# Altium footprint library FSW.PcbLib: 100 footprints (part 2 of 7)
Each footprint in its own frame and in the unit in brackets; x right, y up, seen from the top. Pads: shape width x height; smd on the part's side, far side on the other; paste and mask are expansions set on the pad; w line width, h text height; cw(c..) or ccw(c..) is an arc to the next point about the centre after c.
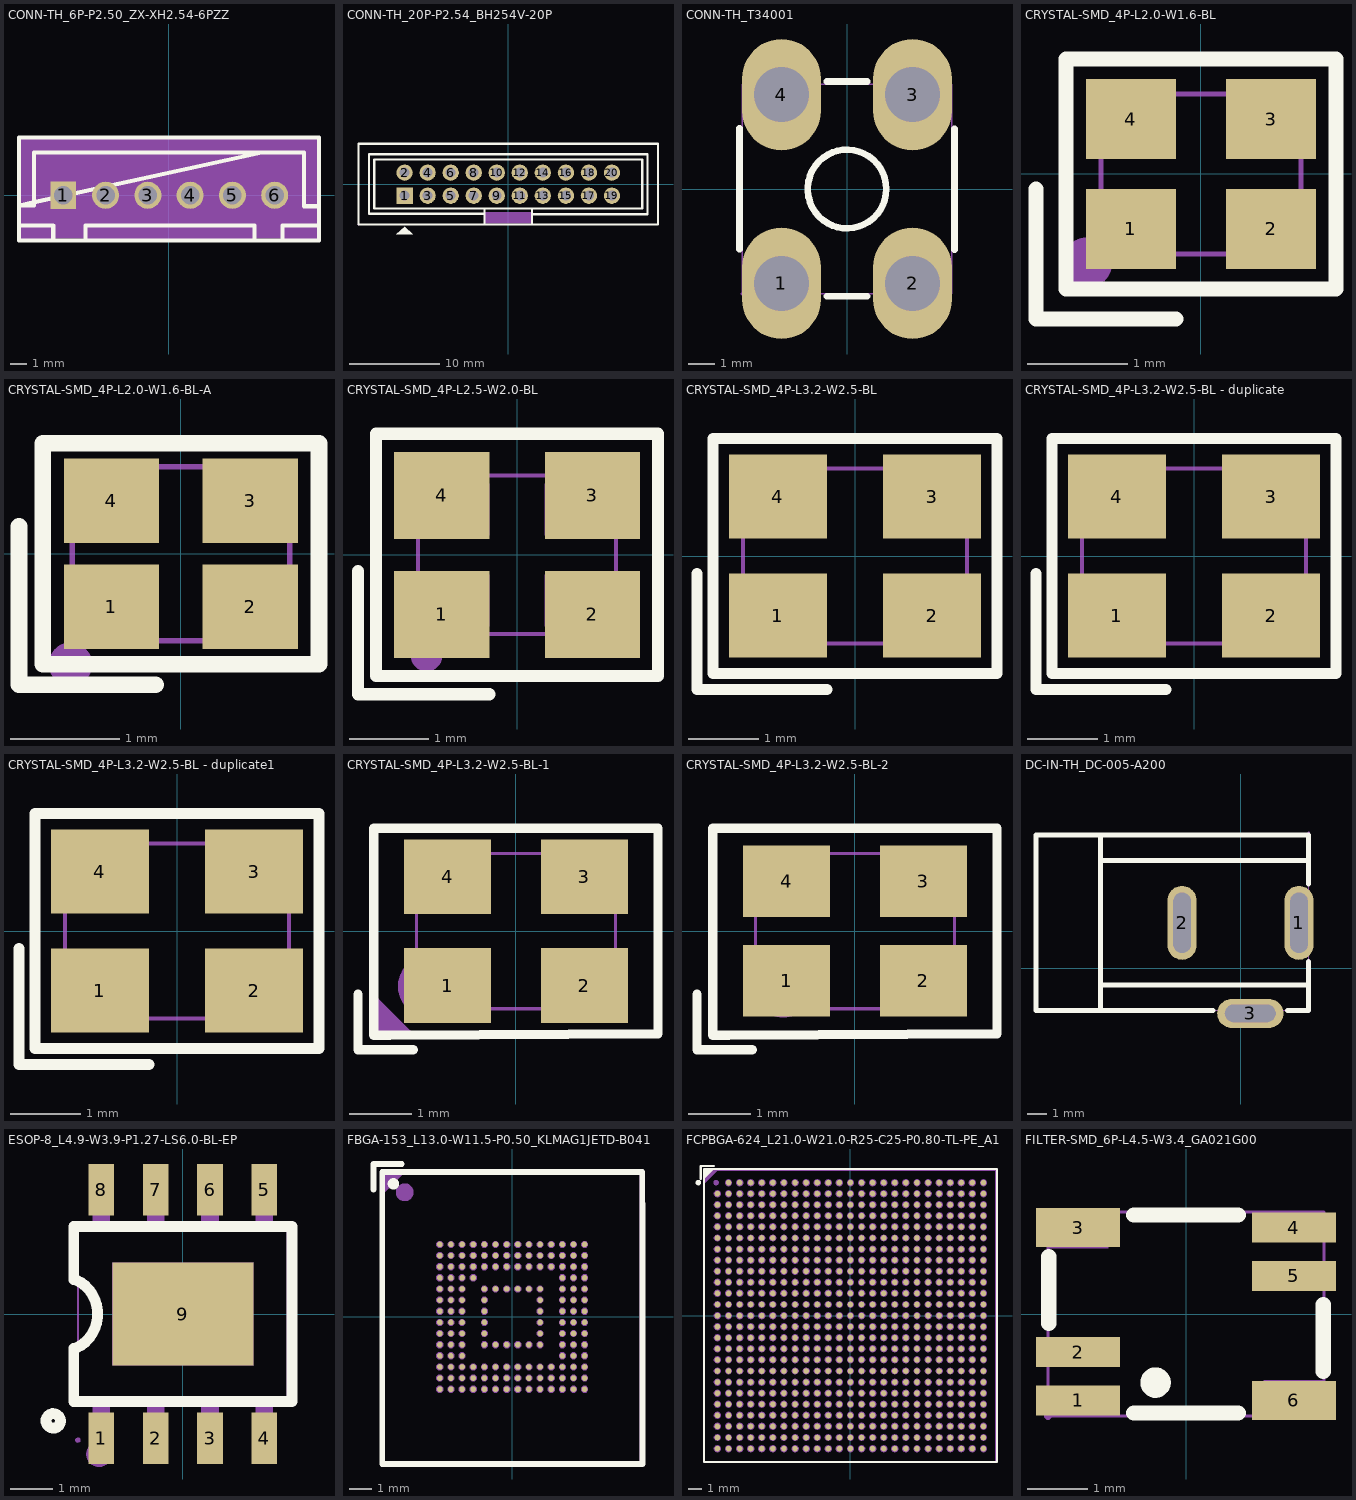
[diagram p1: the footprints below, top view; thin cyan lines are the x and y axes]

## CONN-TH_6P-P2.50_ZX-XH2.54-6PZZ [mm]
pads (6):
  rect 1.524x1.6 hole 1.1 paste-2539.97 mask+0.051: 1(-6.25,0)
  round 1.6 hole 1.1 copper offset 0,0 paste-2539.97 mask+0.051: 2(-3.75,0) 4(1.25,0) 5(3.75,0) 6(6.25,0)
  round 1.6 hole 1.1 paste-2539.97 mask+0.051: 3(-1.25,0)
Top Overlay:
  lines w0.254: -8.87,-1.794 -6.838,-1.794 -6.838,-2.679 ; -4.936,-2.679 -4.936,-1.79 2.56,-1.79 5.06,-1.79 5.06,-2.679 ; 6.718,-2.679 6.718,-1.794 8.75,-1.794 ; 8.871,-0.647 7.982,-0.647 7.982,2.528 5.482,2.528 ; -7.98,-0.41 -7.98,-0.604 -8.869,-0.604 -7.98,-0.41 ; -7.98,-0.41 -7.98,2.528 5.482,2.528 ; -7.98,-0.41 5.482,2.528 ; -8.87,-2.679 -8.87,3.417 6.37,3.417 8.87,3.417 8.87,-2.679 6.37,-2.679 -8.87,-2.679
Mechanical 5:
  region: -8.87,-1.794 -6.838,-1.794 -6.838,-2.679 -8.87,-2.679
  region: -4.936,-1.79 -4.936,-2.676 -4.933,-2.679 4.933,-2.679 4.933,-1.79
  region: 6.718,-1.794 6.718,-2.679 8.87,-2.679 8.87,-1.914 8.87,-1.79 8.75,-1.794
  region: 8.87,-0.635 7.994,-0.635 7.982,-0.647 7.982,2.528 -7.98,2.528 -7.98,-0.604 -8.869,-0.604 -8.869,3.416 -8.87,3.417 8.87,3.417
Mechanical 9:
  region: -8.75,-2.55 -8.75,3.35 8.75,3.35 8.75,-2.55
Mechanical 11:
  region: -8.72,-2.55 -8.72,-2.563 -8.738,-2.58 -8.763,-2.58 -8.781,-2.563 -8.781,-2.55 -8.781,-2.537 -8.763,-2.519 -8.738,-2.519 -8.72,-2.537 -8.72,-2.55
Mechanical 12:
  region: 0.93,0.32 1.57,0.32 1.57,-0.32 0.93,-0.32
  region: -1.57,0.32 -0.93,0.32 -0.93,-0.32 -1.57,-0.32
  region: -4.07,0.32 -3.43,0.32 -3.43,-0.32 -4.07,-0.32
  region: -6.57,0.32 -5.93,0.32 -5.93,-0.32 -6.57,-0.32
  region: 3.43,0.32 4.07,0.32 4.07,-0.32 3.43,-0.32
  region: 5.93,0.32 6.57,0.32 6.57,-0.32 5.93,-0.32

## CONN-TH_20P-P2.54_BH254V-20P [mm]
pads (20):
  rect 1.8x1.8 hole 1.1: 1(-11.43,-1.27)
  round 1.8 hole 1.1: 2(-11.43,1.27) 3(-8.89,-1.27) 4(-8.89,1.27) 5(-6.35,-1.27) 6(-6.35,1.27) 7(-3.81,-1.27) 8(-3.81,1.27) 9(-1.27,-1.27) 10(-1.27,1.27) 11(1.27,-1.27) 12(1.27,1.27) 13(3.81,-1.27) 14(3.81,1.27) 15(6.35,-1.27) 16(6.35,1.27) 17(8.89,-1.27) 18(8.89,1.27) 19(11.43,-1.27) 20(11.43,1.27)
Top Overlay:
  region: -12.344,-5.512 -10.541,-5.512 -11.43,-4.674
  lines w0.254: -15.367,3.293 -15.367,-3.277 -2.616,-3.277 ; -15.358,3.302 15.342,3.302 15.342,-3.268 ; -2.616,-4.394 -2.616,-3.277 ; 2.616,-4.394 2.616,-3.327 ; 15.342,-3.277 15.342,-3.302 2.616,-3.302 2.616,-3.327 ; -2.616,-3.277 -2.616,-2.692 ; -2.616,-2.692 2.616,-2.692 ; -2.616,-2.692 -14.783,-2.692 -14.783,2.718 14.783,2.718 14.783,-2.642 14.783,-2.692 2.616,-2.692 ; 2.616,-3.327 2.616,-2.692 ; -16.51,-4.445 -16.51,4.445 16.51,4.445 16.51,-4.445 -16.51,-4.445
Mechanical 2:
  region: -2.515,-3.099 2.489,-3.099 2.489,-4.318 -2.515,-4.318
Mechanical 6:
  lines w0.051: -16.51,-4.445 16.51,-4.445 16.51,4.445 -16.51,4.445 -16.51,-4.445
Mechanical 8:
  region: -16.45,-4.445 -16.45,-4.47 -16.485,-4.505 -16.535,-4.505 -16.57,-4.47 -16.57,-4.445 -16.57,-4.42 -16.535,-4.385 -16.485,-4.385 -16.45,-4.42 -16.45,-4.445
Mechanical 9:
  region: -11.75,-0.95 -11.11,-0.95 -11.11,-1.59 -11.75,-1.59
  region: -11.75,1.59 -11.11,1.59 -11.11,0.95 -11.75,0.95
  region: -9.21,-0.95 -8.57,-0.95 -8.57,-1.59 -9.21,-1.59
  region: -9.21,1.59 -8.57,1.59 -8.57,0.95 -9.21,0.95
  region: -6.67,-0.95 -6.03,-0.95 -6.03,-1.59 -6.67,-1.59
  region: -6.67,1.59 -6.03,1.59 -6.03,0.95 -6.67,0.95
  region: -4.13,-0.95 -3.49,-0.95 -3.49,-1.59 -4.13,-1.59
  region: -4.13,1.59 -3.49,1.59 -3.49,0.95 -4.13,0.95
  region: -1.59,-0.95 -0.95,-0.95 -0.95,-1.59 -1.59,-1.59
  region: -1.59,1.59 -0.95,1.59 -0.95,0.95 -1.59,0.95
  region: 0.95,-0.95 1.59,-0.95 1.59,-1.59 0.95,-1.59
  region: 0.95,1.59 1.59,1.59 1.59,0.95 0.95,0.95
  region: 3.49,-0.95 4.13,-0.95 4.13,-1.59 3.49,-1.59
  region: 3.49,1.59 4.13,1.59 4.13,0.95 3.49,0.95
  region: 6.03,-0.95 6.67,-0.95 6.67,-1.59 6.03,-1.59
  region: 6.03,1.59 6.67,1.59 6.67,0.95 6.03,0.95
  region: 8.57,-0.95 9.21,-0.95 9.21,-1.59 8.57,-1.59
  region: 8.57,1.59 9.21,1.59 9.21,0.95 8.57,0.95
  region: 11.11,-0.95 11.75,-0.95 11.75,-1.59 11.11,-1.59
  region: 11.11,1.59 11.75,1.59 11.75,0.95 11.11,0.95

## CONN-TH_T34001 [mm]
pads (4):
  oval 3x4.25 hole 2.1: 1(-2.5,-3.6) 2(2.5,-3.6) 3(2.5,3.6) 4(-2.5,3.6)
Top Overlay:
  circle w0.254: c0,0 r1.5
  lines w0.254: -4.1,-2.3 -4.1,2.318 ; -0.769,-4.1 0.769,-4.1 ; -0.769,4.1 0.769,4.1 ; 4.1,-2.318 4.1,2.3
Mechanical 6:
  lines w0.051: -4,-4 4,-4 4,4 -4,4 -4,-4
Mechanical 8:
  region: -3.939,-4 -3.939,-4.025 -3.975,-4.061 -4.025,-4.061 -4.061,-4.025 -4.061,-4 -4.061,-3.975 -4.025,-3.939 -3.975,-3.939 -3.939,-3.975 -3.939,-4 -3.94,-4
Mechanical 9:
  region: 1.75,3.2 1.75,4 3.25,4 3.25,3.2
  region: 1.75,-4 1.75,-3.2 3.25,-3.2 3.25,-4
  region: -3.25,-4 -3.25,-3.2 -1.75,-3.2 -1.75,-4
  region: -3.25,3.2 -3.25,4 -1.75,4 -1.75,3.2

## CRYSTAL-SMD_4P-L2.0-W1.6-BL [mm]
pads (4):
  rect 0.9x0.8 smd: 1(-0.7,-0.55) 2(0.7,-0.55) 3(0.7,0.55) 4(-0.7,0.55)
Top Overlay:
  lines w0.152: -1.65,-0.15 -1.65,-1.45 -0.25,-1.45 ; -1.35,-1.15 -1.35,1.15 1.35,1.15 1.35,-1.15 -1.35,-1.15
Mechanical 2:
  circle w0.254: c-1.143,-0.889 r0.127
Mechanical 6:
  lines w0.051: -1,-0.8 1,-0.8 1,0.8 -1,0.8 -1,-0.8
Mechanical 8:
  region: -0.94,-0.8 -0.94,-0.825 -0.975,-0.86 -1.025,-0.86 -1.06,-0.825 -1.06,-0.8 -1.06,-0.775 -1.025,-0.74 -0.975,-0.74 -0.94,-0.775 -0.94,-0.8
Mechanical 9:
  region: 0.95,0.75 0.95,0.275 0.375,0.275 0.375,0.75
  region: 0.95,-0.275 0.95,-0.75 0.375,-0.75 0.375,-0.275
  region: -0.95,-0.75 -0.95,-0.275 -0.375,-0.275 -0.375,-0.75
  region: -0.95,0.275 -0.95,0.75 -0.375,0.75 -0.375,0.275

## CRYSTAL-SMD_4P-L2.0-W1.6-BL-A [mm]
pads (4):
  rect 0.875x0.775 smd: 1(-0.638,-0.488) 2(0.638,-0.488) 3(0.638,0.488) 4(-0.638,0.488)
Top Overlay:
  lines w0.152: -1.488,0.254 -1.488,-1.204 -0.231,-1.204 ; -1.27,-1.016 -1.27,1.016 1.27,1.016 1.27,-1.016 -1.27,-1.016
Mechanical 2:
  circle w0.2: c-1.016,-1.016 r0.1
Mechanical 6:
  lines w0.051: -1,-0.8 -1,0.8 1,0.8 1,-0.8 -1,-0.8
Mechanical 8:
  region: -0.94,-0.8 -0.94,-0.825 -0.975,-0.86 -1.025,-0.86 -1.06,-0.825 -1.06,-0.8 -1.06,-0.775 -1.025,-0.74 -0.975,-0.74 -0.94,-0.775 -0.94,-0.8
Mechanical 9:
  region: -1,-0.225 -0.325,-0.225 -0.325,-0.8 -1,-0.8
  region: 0.325,-0.225 1,-0.225 1,-0.8 0.325,-0.8
  region: 0.325,0.8 1,0.8 1,0.225 0.325,0.225
  region: -1,0.8 -0.325,0.8 -0.325,0.225 -1,0.225
3D body "CRYSTAL-SMD_4P-L2.0-W1.6-BL-A.step": height 0.5, standoff -0.01, extent -1,-0.8 1,0.8

## CRYSTAL-SMD_4P-L2.5-W2.0-BL [mm]
pads (4):
  rect 1.2x1.1 smd: 1(-0.95,-0.75) 2(0.95,-0.75) 3(0.95,0.75) 4(-0.95,0.75)
Top Overlay:
  lines w0.152: -2.007,-0.201 -2.007,-1.758 -0.351,-1.758 ; -1.779,-1.529 -1.779,1.529 1.779,1.529 1.779,-1.529 -1.779,-1.529
Mechanical 2:
  circle w0.2: c-1.143,-1.27 r0.1
Mechanical 6:
  lines w0.051: -1.25,-1 -1.25,1 1.25,1 1.25,-1 -1.25,-1
Mechanical 8:
  region: -1.19,-1 -1.19,-1.025 -1.225,-1.06 -1.275,-1.06 -1.31,-1.025 -1.31,-1 -1.31,-0.975 -1.275,-0.94 -1.225,-0.94 -1.19,-0.975 -1.19,-1
Mechanical 9:
  region: 0.35,-0.25 1.15,-0.25 1.15,-0.9 0.35,-0.9
  region: -0.35,-0.9 -1.15,-0.9 -1.15,-0.25 -0.35,-0.25
  region: -0.35,0.25 -1.15,0.25 -1.15,0.9 -0.35,0.9
  region: 1.15,0.25 0.35,0.25 0.35,0.9 1.15,0.9

## CRYSTAL-SMD_4P-L3.2-W2.5-BL [mm]
pads (4):
  rect 1.4x1.2 smd: 1(-1.1,-0.85) 2(1.1,-0.85) 3(1.1,0.85) 4(-1.1,0.85)
Top Overlay:
  lines w0.152: -2.257,-0.25 -2.257,-1.907 -0.4,-1.907 ; -2.029,-1.678 -2.029,1.679 2.029,1.679 2.029,-1.678 -2.029,-1.678
Mechanical 2:
  circle w0.254: c-1.27,-0.889 r0.127
Mechanical 6:
  lines w0.051: -1.6,-1.25 -1.6,1.25 1.6,1.25 1.6,-1.25 -1.6,-1.25
Mechanical 8:
  region: -1.539,-1.25 -1.539,-1.275 -1.575,-1.311 -1.625,-1.311 -1.661,-1.275 -1.661,-1.25 -1.661,-1.225 -1.625,-1.189 -1.575,-1.189 -1.539,-1.225 -1.539,-1.25 -1.54,-1.25
Mechanical 9:
  region: -1.5,1.15 -0.6,1.15 -0.6,0.35 -1.5,0.35
  region: 0.6,1.15 1.5,1.15 1.5,0.35 0.6,0.35
  region: 0.6,-0.35 1.5,-0.35 1.5,-1.15 0.6,-1.15
  region: -1.5,-0.35 -0.6,-0.35 -0.6,-1.15 -1.5,-1.15

## CRYSTAL-SMD_4P-L3.2-W2.5-BL - duplicate [mm]
pads (4):
  rect 1.4x1.2 smd: 1(-1.1,-0.85) 2(1.1,-0.85) 3(1.1,0.85) 4(-1.1,0.85)
Top Overlay:
  lines w0.152: -2.257,-0.25 -2.257,-1.907 -0.4,-1.907 ; -2.029,-1.678 2.029,-1.678 2.029,1.679 -2.029,1.679 -2.029,-1.678
Mechanical 2:
  circle w0.254: c-1.27,-0.889 r0.127
Mechanical 6:
  lines w0.051: -1.6,-1.25 1.6,-1.25 1.6,1.25 -1.6,1.25 -1.6,-1.25
Mechanical 8:
  region: -1.54,-1.25 -1.54,-1.275 -1.575,-1.31 -1.625,-1.31 -1.66,-1.275 -1.66,-1.25 -1.66,-1.225 -1.625,-1.19 -1.575,-1.19 -1.54,-1.225 -1.54,-1.25
Mechanical 9:
  region: -1.5,-0.35 -0.6,-0.35 -0.6,-1.15 -1.5,-1.15
  region: 0.6,-0.35 1.5,-0.35 1.5,-1.15 0.6,-1.15
  region: 0.6,1.15 1.5,1.15 1.5,0.35 0.6,0.35
  region: -1.5,1.15 -0.6,1.15 -0.6,0.35 -1.5,0.35

## CRYSTAL-SMD_4P-L3.2-W2.5-BL - duplicate1 [mm]
pads (4):
  rect 1.4x1.2 smd: 1(-1.1,-0.85) 2(1.1,-0.85) 3(1.1,0.85) 4(-1.1,0.85)
Top Overlay:
  lines w0.152: -2.257,-0.25 -2.257,-1.907 -0.4,-1.907 ; -2.029,-1.678 2.029,-1.678 2.029,1.679 -2.029,1.679 -2.029,-1.678
Mechanical 2:
  circle w0.254: c-1.27,-0.889 r0.127
Mechanical 6:
  lines w0.051: -1.6,-1.25 1.6,-1.25 1.6,1.25 -1.6,1.25 -1.6,-1.25
Mechanical 8:
  region: -1.54,-1.25 -1.54,-1.275 -1.575,-1.31 -1.625,-1.31 -1.66,-1.275 -1.66,-1.25 -1.66,-1.225 -1.625,-1.19 -1.575,-1.19 -1.54,-1.225 -1.54,-1.25
Mechanical 9:
  region: -1.5,-0.35 -0.6,-0.35 -0.6,-1.15 -1.5,-1.15
  region: 0.6,-0.35 1.5,-0.35 1.5,-1.15 0.6,-1.15
  region: 0.6,1.15 1.5,1.15 1.5,0.35 0.6,0.35
  region: -1.5,1.15 -0.6,1.15 -0.6,0.35 -1.5,0.35

## CRYSTAL-SMD_4P-L3.2-W2.5-BL-1 [mm]
pads (4):
  rect 1.4x1.2 smd: 1(-1.1,-0.875) 2(1.1,-0.875) 3(1.1,0.875) 4(-1.1,0.875)
Top Overlay:
  lines w0.152: -2.54,-1.016 -2.54,-1.778 -2.54,-1.905 -1.651,-1.905 ; -2.286,-1.679 -2.286,1.651 2.286,1.651 2.286,0 2.286,-1.651 -2.03,-1.679 -2.286,-1.679
Mechanical 2:
  circle w0.5: c-1.397,-0.889 r0.25
  region: -2.286,-1.016 -2.286,-1.651 -1.651,-1.651
Mechanical 6:
  lines w0.051: -1.6,-1.25 1.6,-1.25 1.6,1.25 -1.6,1.25 -1.6,-1.25
Mechanical 8:
  region: -1.54,-1.25 -1.54,-1.275 -1.575,-1.31 -1.625,-1.31 -1.66,-1.275 -1.66,-1.25 -1.66,-1.225 -1.625,-1.19 -1.575,-1.19 -1.54,-1.225 -1.54,-1.25
Mechanical 9:
  region: 0.45,1.15 1.5,1.15 1.5,0.35 0.45,0.35
  region: -1.5,1.15 -0.45,1.15 -0.45,0.35 -1.5,0.35
  region: -1.5,-0.35 -0.45,-0.35 -0.45,-1.15 -1.5,-1.15
  region: 0.45,-0.35 1.5,-0.35 1.5,-1.15 0.45,-1.15
3D body "CRYSTAL-SMD_4P-L3.2-W2.5-BL-1.step": height 0.71, standoff -0.01, extent -1.6,-1.25 1.6,1.25

## CRYSTAL-SMD_4P-L3.2-W2.5-BL-2 [mm]
pads (4):
  rect 1.4x1.15 smd: 1(-1.1,-0.8) 2(1.1,-0.8) 3(1.1,0.8) 4(-1.1,0.8)
Top Overlay:
  lines w0.152: -2.54,-1.016 -2.54,-1.778 -2.54,-1.905 -1.651,-1.905 ; -2.286,-1.679 -2.03,-1.679 2.286,-1.651 2.286,0 2.286,1.651 -2.286,1.651 -2.286,-1.679
Mechanical 2:
  circle w0.5: c-1.143,-0.889 r0.25
Mechanical 6:
  lines w0.051: -1.6,-1.25 -1.6,1.25 1.6,1.25 1.6,-1.25 -1.6,-1.25
Mechanical 8:
  region: -1.54,-1.25 -1.54,-1.275 -1.575,-1.31 -1.625,-1.31 -1.66,-1.275 -1.66,-1.25 -1.66,-1.225 -1.625,-1.19 -1.575,-1.19 -1.54,-1.225 -1.54,-1.25
Mechanical 9:
  region: 0.5,1.15 1.5,1.15 1.5,0.35 0.5,0.35
  region: -1.5,1.15 -0.5,1.15 -0.5,0.35 -1.5,0.35
  region: -1.5,-0.35 -0.5,-0.35 -0.5,-1.15 -1.5,-1.15
  region: 0.5,-0.35 1.5,-0.35 1.5,-1.15 0.5,-1.15

## DC-IN-TH_DC-005-A200 [mm]
pads (3):
  oval 1.5x3.8 hole 0.9 slot 3.1 at 90 deg copper offset -0.001,0: 1(3.001,2.325)
  oval 1.5x3.8 hole 0.9 slot 3.1 at 90 deg copper offset 0,0: 2(-3,2.325)
  oval 3.4x1.5 hole 0.9 slot 2.6 at 0 deg copper offset 0,-0.001: 3(0.5,-2.325)
Top Overlay:
  lines w0.254: -7.2,-2.174 -7.2,6.826 ; -7.12,-0.874 3.5,-0.874 ; -7.12,5.525 3.5,5.525 ; -1.419,-2.174 -10.5,-2.174 -10.5,6.826 3.5,6.826 3.5,4.319 ; 2.42,-2.174 3.5,-2.174 3.5,0.332
Mechanical 6:
  lines w0.051: -10.5,-2.175 -10.5,6.825 3.5,6.825 3.5,-2.175 -10.5,-2.175
Mechanical 8:
  region: 3.56,6.952 3.56,6.928 3.525,6.893 3.475,6.893 3.44,6.928 3.44,6.952 3.44,6.977 3.475,7.012 3.525,7.012 3.56,6.977 3.56,6.952
Mechanical 9:
  region: -0.35,-1.964 1.35,-1.964 1.35,-2.685 -0.35,-2.685
  region: -2.64,3.426 -2.64,1.225 -3.36,1.225 -3.36,3.426
  region: 2.64,1.225 2.64,3.426 3.36,3.426 3.36,1.225
3D body "DC-IN-TH_DC-005-A200.step": height 11, standoff -4.1, extent -10.621,-2.516 3.429,6.834

## ESOP-8_L4.9-W3.9-P1.27-LS6.0-BL-EP [mil]
pads (9):
  rect 23.6x47.2 smd: 1(-75,-114.5) 2(-25,-114.5) 3(25,-114.5) 4(75,-114.5) 5(75,114.5) 6(25,114.5) 7(-25,114.5) 8(-75,114.5)
  rect 129.9x94.5 smd: 9(0,0)
Top Overlay:
  lines w10: -100.4,-31.5 -100.4,-80.7 100.4,-80.7 100.4,80.7 -100.4,80.7 -100.4,31.5 ; -98.4,-31.5 -93.9,-28.9 -89.7,-25.7 -86.1,-21.8 -83.2,-17.5 -80.9,-12.8 -79.3,-7.8 -78.5,-2.6 -78.5,2.6 -79.3,7.8 -80.9,12.8 -83.2,17.6 -86.1,21.9 -89.7,25.7 -93.9,28.9 -98.4,31.5 ; -125.9,-99.5 -125.2,-101.6 -123.8,-103.3 -122,-104.5 -119.9,-105.1 -117.7,-104.9 -115.6,-104 -114,-102.5 -113,-100.6 -112.6,-98.4 -113,-96.2 -114,-94.3 -115.6,-92.8 -117.7,-91.9 -119.9,-91.7 -122,-92.3 -123.8,-93.5 -125.2,-95.2 -125.9,-97.3 -125.9,-99.5
Mechanical 2:
  lines w11.8: -83.1,-129.1 -82.7,-131.1 -81.7,-132.9 -80.1,-134.2 -78.2,-134.9 -76.1,-134.9 -74.2,-134.2 -72.6,-132.9 -71.6,-131.1 -71.3,-129.1 -71.6,-127.1 -72.6,-125.3 -74.2,-124 -76.1,-123.3 -78.2,-123.3 -80.1,-124 -81.7,-125.3 -82.7,-127.1 -83.1,-129.1
Mechanical 6:
  lines w2: -96.5,-76.7 96.4,-76.7 96.4,76.8 -96.5,76.8 -96.5,-76.7
Mechanical 7:
  region: -82.9,76.4 -82.9,91 -67.1,91 -67.1,76.4
  region: -32.9,76.4 -32.9,91 -17.1,91 -17.1,76.4
  region: 17.1,76.4 17.1,91 32.9,91 32.9,76.4
  region: 67.1,76.4 67.1,91 82.9,91 82.9,76.4
  region: -82.9,-90.9 -82.9,-76.4 -67.1,-76.4 -67.1,-90.9
  region: -32.9,-90.9 -32.9,-76.4 -17.1,-76.4 -17.1,-90.9
  region: 17.1,-90.9 17.1,-76.4 32.9,-76.4 32.9,-90.9
  region: 67.1,-90.9 67.1,-76.4 82.9,-76.4 82.9,-90.9
Mechanical 8:
  region: -94.3,-116.1 -94.6,-117.4 -95.6,-118.3 -97,-118.5 -98.2,-117.9 -98.9,-116.8 -98.9,-115.5 -98.2,-114.3 -97,-113.8 -95.6,-114 -94.6,-114.8
Mechanical 9:
  region: -82.9,90.6 -82.9,116.2 -67.1,116.2 -67.1,90.6
  region: -32.9,90.6 -32.9,116.2 -17.1,116.2 -17.1,90.6
  region: 17.1,90.6 17.1,116.2 32.9,116.2 32.9,90.6
  region: 67.1,90.6 67.1,116.2 82.9,116.2 82.9,90.6
  region: -82.9,-116.1 -82.9,-90.5 -67.1,-90.5 -67.1,-116.1
  region: -32.9,-116.1 -32.9,-90.5 -17.1,-90.5 -17.1,-116.1
  region: 17.1,-116.1 17.1,-90.5 32.9,-90.5 32.9,-116.1
  region: 67.1,-116.1 67.1,-90.5 82.9,-90.5 82.9,-116.1
  region: 65,-47.2 -65,-47.2 -65,47.3 65,47.3

## FBGA-153_L13.0-W11.5-P0.50_KLMAG1JETD-B041 [mm]
pads (153):
  round 0.25 smd paste-100 mask+0.05: A1(-3.25,3.25) A2(-2.75,3.25) A3(-2.25,3.25) A4(-1.75,3.25) A5(-1.25,3.25) A6(-0.75,3.25) A7(-0.25,3.25) A8(0.25,3.25) A9(0.75,3.25) A10(1.25,3.25) A11(1.75,3.25) A12(2.25,3.25) A13(2.75,3.25) A14(3.25,3.25) B1(-3.25,2.75) B2(-2.75,2.75) B3(-2.25,2.75) B4(-1.75,2.75) B5(-1.25,2.75) B6(-0.75,2.75) B7(-0.25,2.75) B8(0.25,2.75) B9(0.75,2.75) B10(1.25,2.75) B11(1.75,2.75) B12(2.25,2.75) B13(2.75,2.75) B14(3.25,2.75) C1(-3.25,2.25) C2(-2.75,2.25) C3(-2.25,2.25) C4(-1.75,2.25) C5(-1.25,2.25) C6(-0.75,2.25) C7(-0.25,2.25) C8(0.25,2.25) C9(0.75,2.25) C10(1.25,2.25) C11(1.75,2.25) C12(2.25,2.25) C13(2.75,2.25) C14(3.25,2.25) D1(-3.25,1.75) D2(-2.75,1.75) D3(-2.25,1.75) D4(-1.75,1.75) D12(2.25,1.75) D13(2.75,1.75) D14(3.25,1.75) E1(-3.25,1.25) E2(-2.75,1.25) E3(-2.25,1.25) E5(-1.25,1.25) E6(-0.75,1.25) E7(-0.25,1.25) E8(0.25,1.25) E9(0.75,1.25) E10(1.25,1.25) E12(2.25,1.25) E13(2.75,1.25) E14(3.25,1.25) F1(-3.25,0.75) F2(-2.75,0.75) F3(-2.25,0.75) F5(-1.25,0.75) F10(1.25,0.75) F12(2.25,0.75) F13(2.75,0.75) F14(3.25,0.75) G1(-3.25,0.25) G2(-2.75,0.25) G3(-2.25,0.25) G5(-1.25,0.25) G10(1.25,0.25) G12(2.25,0.25) G13(2.75,0.25) G14(3.25,0.25) H1(-3.25,-0.25) H2(-2.75,-0.25) H3(-2.25,-0.25) H5(-1.25,-0.25) H10(1.25,-0.25) H12(2.25,-0.25) H13(2.75,-0.25) H14(3.25,-0.25) J1(-3.25,-0.75) J2(-2.75,-0.75) J3(-2.25,-0.75) J5(-1.25,-0.75) J10(1.25,-0.75) J12(2.25,-0.75) J13(2.75,-0.75) J14(3.25,-0.75) K1(-3.25,-1.25) K2(-2.75,-1.25) K3(-2.25,-1.25) K5(-1.25,-1.25) K6(-0.75,-1.25) K7(-0.25,-1.25) K8(0.25,-1.25) K9(0.75,-1.25) K10(1.25,-1.25) K12(2.25,-1.25) K13(2.75,-1.25) K14(3.25,-1.25) L1(-3.25,-1.75) L2(-2.75,-1.75) L3(-2.25,-1.75) L12(2.25,-1.75) L13(2.75,-1.75) L14(3.25,-1.75) M1(-3.25,-2.25) M2(-2.75,-2.25) M3(-2.25,-2.25) M4(-1.75,-2.25) M5(-1.25,-2.25) M6(-0.75,-2.25) M7(-0.25,-2.25) M8(0.25,-2.25) M9(0.75,-2.25) M10(1.25,-2.25) M11(1.75,-2.25) M12(2.25,-2.25) M13(2.75,-2.25) M14(3.25,-2.25) N1(-3.25,-2.75) N2(-2.75,-2.75) N3(-2.25,-2.75) N4(-1.75,-2.75) N5(-1.25,-2.75) N6(-0.75,-2.75) N7(-0.25,-2.75) N8(0.25,-2.75) N9(0.75,-2.75) N10(1.25,-2.75) N11(1.75,-2.75) N12(2.25,-2.75) N13(2.75,-2.75) N14(3.25,-2.75) P1(-3.25,-3.25) P2(-2.75,-3.25) P3(-2.25,-3.25) P4(-1.75,-3.25) P5(-1.25,-3.25) P6(-0.75,-3.25) P7(-0.25,-3.25) P8(0.25,-3.25) P9(0.75,-3.25) P10(1.25,-3.25) P11(1.75,-3.25) P12(2.25,-3.25) P13(2.75,-3.25) P14(3.25,-3.25)
Top Overlay:
  circle w0.254: c-5.334,5.969 r0.127
  lines w0.254: -6.223,5.715 -6.223,6.858 -4.953,6.858 ; -5.841,-6.605 5.843,-6.605 5.843,5.079 ; -5.841,-6.5 -5.841,6.5 5.842,6.5 5.842,5.079
Top Paste:
  drawing of 153 lines, arcs and shapes, not listed
Mechanical 4:
  circle w0.4: c-4.826,5.588 r0.2
  region: -4.826,6.477 -5.715,6.477 -5.715,5.588
Mechanical 8:
  lines w0.051: -5.75,-6.5 5.75,-6.5 5.75,6.5 -5.75,6.5 -5.75,-6.5
Mechanical 10:
  region: -5.69,6.5 -5.69,6.475 -5.725,6.44 -5.775,6.44 -5.81,6.475 -5.81,6.5 -5.81,6.525 -5.775,6.56 -5.725,6.56 -5.69,6.525 -5.69,6.5
Mechanical 11:
  drawing of 153 lines, arcs and shapes, not listed
3D body "VFBGA-153_L13.0-W11.5-P0.50-BL_ISSI_IS2XES0XG-XXXX.step": height 0.99, standoff 0.03, extent -5.785,-6.5 5.715,6.5

## FCPBGA-624_L21.0-W21.0-R25-C25-P0.80-TL-PE_A1 [mm]
pads (624):
  round 0.4 smd paste+0 mask+0.05: A2(-8.8,9.6) A3(-8,9.6) A4(-7.2,9.6) A5(-6.4,9.6) A6(-5.6,9.6) A7(-4.8,9.6) A8(-4,9.6) A9(-3.2,9.6) A10(-2.4,9.6) A11(-1.6,9.6) A12(-0.8,9.6) A13(0,9.6) A14(0.8,9.6) A15(1.6,9.6) A16(2.4,9.6) A17(3.2,9.6) A18(4,9.6) A19(4.8,9.6) A20(5.6,9.6) A21(6.4,9.6) A22(7.2,9.6) A23(8,9.6) A24(8.8,9.6) A25(9.6,9.6) AA1(-9.6,-6.4) AA2(-8.8,-6.4) AA3(-8,-6.4) AA4(-7.2,-6.4) AA5(-6.4,-6.4) AA6(-5.6,-6.4) AA7(-4.8,-6.4) AA8(-4,-6.4) AA9(-3.2,-6.4) AA10(-2.4,-6.4) AA11(-1.6,-6.4) AA12(-0.8,-6.4) AA13(0,-6.4) AA14(0.8,-6.4) AA15(1.6,-6.4) AA16(2.4,-6.4) AA17(3.2,-6.4) AA18(4,-6.4) AA19(4.8,-6.4) AA20(5.6,-6.4) AA21(6.4,-6.4) AA22(7.2,-6.4) AA23(8,-6.4) AA24(8.8,-6.4) AA25(9.6,-6.4) AB1(-9.6,-7.2) AB2(-8.8,-7.2) AB3(-8,-7.2) AB4(-7.2,-7.2) AB5(-6.4,-7.2) AB6(-5.6,-7.2) AB7(-4.8,-7.2) AB8(-4,-7.2) AB9(-3.2,-7.2) AB10(-2.4,-7.2) AB11(-1.6,-7.2) AB12(-0.8,-7.2) AB13(0,-7.2) AB14(0.8,-7.2) AB15(1.6,-7.2) AB16(2.4,-7.2) AB17(3.2,-7.2) AB18(4,-7.2) AB19(4.8,-7.2) AB20(5.6,-7.2) AB21(6.4,-7.2) AB22(7.2,-7.2) AB23(8,-7.2) AB24(8.8,-7.2) AB25(9.6,-7.2) AC1(-9.6,-8) AC2(-8.8,-8) AC3(-8,-8) AC4(-7.2,-8) AC5(-6.4,-8) AC6(-5.6,-8) AC7(-4.8,-8) AC8(-4,-8) AC9(-3.2,-8) AC10(-2.4,-8) AC11(-1.6,-8) AC12(-0.8,-8) AC13(0,-8) AC14(0.8,-8) AC15(1.6,-8) AC16(2.4,-8) AC17(3.2,-8) AC18(4,-8) AC19(4.8,-8) AC20(5.6,-8) AC21(6.4,-8) AC22(7.2,-8) AC23(8,-8) AC24(8.8,-8) AC25(9.6,-8) AD1(-9.6,-8.8) AD2(-8.8,-8.8) AD3(-8,-8.8) AD4(-7.2,-8.8) AD5(-6.4,-8.8) AD6(-5.6,-8.8) AD7(-4.8,-8.8) AD8(-4,-8.8) AD9(-3.2,-8.8) AD10(-2.4,-8.8) AD11(-1.6,-8.8) AD12(-0.8,-8.8) AD13(0,-8.8) AD14(0.8,-8.8) AD15(1.6,-8.8) AD16(2.4,-8.8) AD17(3.2,-8.8) AD18(4,-8.8) AD19(4.8,-8.8) AD20(5.6,-8.8) AD21(6.4,-8.8) AD22(7.2,-8.8) AD23(8,-8.8) AD24(8.8,-8.8) AD25(9.6,-8.8) AE1(-9.6,-9.6) AE2(-8.8,-9.6) AE3(-8,-9.6) AE4(-7.2,-9.6) AE5(-6.4,-9.6) AE6(-5.6,-9.6) AE7(-4.8,-9.6) AE8(-4,-9.6) AE9(-3.2,-9.6) AE10(-2.4,-9.6) AE11(-1.6,-9.6) AE12(-0.8,-9.6) AE13(0,-9.6) AE14(0.8,-9.6) AE15(1.6,-9.6) AE16(2.4,-9.6) AE17(3.2,-9.6) AE18(4,-9.6) AE19(4.8,-9.6) AE20(5.6,-9.6) AE21(6.4,-9.6) AE22(7.2,-9.6) AE23(8,-9.6) AE24(8.8,-9.6) AE25(9.6,-9.6) B1(-9.6,8.8) B2(-8.8,8.8) B3(-8,8.8) B4(-7.2,8.8) B5(-6.4,8.8) B6(-5.6,8.8) B7(-4.8,8.8) B8(-4,8.8) B9(-3.2,8.8) B10(-2.4,8.8) B11(-1.6,8.8) B12(-0.8,8.8) B13(0,8.8) B14(0.8,8.8) B15(1.6,8.8) B16(2.4,8.8) B17(3.2,8.8) B18(4,8.8) B19(4.8,8.8) B20(5.6,8.8) B21(6.4,8.8) B22(7.2,8.8) B23(8,8.8) B24(8.8,8.8) B25(9.6,8.8) C1(-9.6,8) C2(-8.8,8) C3(-8,8) C4(-7.2,8) C5(-6.4,8) C6(-5.6,8) C7(-4.8,8) C8(-4,8) C9(-3.2,8) C10(-2.4,8) C11(-1.6,8) C12(-0.8,8) C13(0,8) C14(0.8,8) C15(1.6,8) C16(2.4,8) C17(3.2,8) C18(4,8) C19(4.8,8) C20(5.6,8) C21(6.4,8) C22(7.2,8) C23(8,8) C24(8.8,8) C25(9.6,8) D1(-9.6,7.2) D2(-8.8,7.2) D3(-8,7.2) D4(-7.2,7.2) D5(-6.4,7.2) D6(-5.6,7.2) D7(-4.8,7.2) D8(-4,7.2) D9(-3.2,7.2) D10(-2.4,7.2) D11(-1.6,7.2) D12(-0.8,7.2) D13(0,7.2) D14(0.8,7.2) D15(1.6,7.2) D16(2.4,7.2) D17(3.2,7.2) D18(4,7.2) D19(4.8,7.2) D20(5.6,7.2) D21(6.4,7.2) D22(7.2,7.2) D23(8,7.2) D24(8.8,7.2) D25(9.6,7.2) E1(-9.6,6.4) E2(-8.8,6.4) E3(-8,6.4) E4(-7.2,6.4) E5(-6.4,6.4) E6(-5.6,6.4) E7(-4.8,6.4) E8(-4,6.4) E9(-3.2,6.4) E10(-2.4,6.4) E11(-1.6,6.4) E12(-0.8,6.4) E13(0,6.4) E14(0.8,6.4) E15(1.6,6.4) E16(2.4,6.4) E17(3.2,6.4) E18(4,6.4) E19(4.8,6.4) E20(5.6,6.4) E21(6.4,6.4) E22(7.2,6.4) E23(8,6.4) E24(8.8,6.4) E25(9.6,6.4) F1(-9.6,5.6) F2(-8.8,5.6) F3(-8,5.6) F4(-7.2,5.6) F5(-6.4,5.6) F6(-5.6,5.6) F7(-4.8,5.6) F8(-4,5.6) F9(-3.2,5.6) F10(-2.4,5.6) F11(-1.6,5.6) F12(-0.8,5.6) F13(0,5.6) F14(0.8,5.6) F15(1.6,5.6) F16(2.4,5.6) F17(3.2,5.6) F18(4,5.6) F19(4.8,5.6) F20(5.6,5.6) F21(6.4,5.6) F22(7.2,5.6) F23(8,5.6) F24(8.8,5.6) F25(9.6,5.6) G1(-9.6,4.8) G2(-8.8,4.8) G3(-8,4.8) G4(-7.2,4.8) G5(-6.4,4.8) G6(-5.6,4.8) G7(-4.8,4.8) G8(-4,4.8) G9(-3.2,4.8) G10(-2.4,4.8) G11(-1.6,4.8) G12(-0.8,4.8) G13(0,4.8) G14(0.8,4.8) G15(1.6,4.8) G16(2.4,4.8) G17(3.2,4.8) G18(4,4.8) G19(4.8,4.8) G20(5.6,4.8) G21(6.4,4.8) G22(7.2,4.8) G23(8,4.8) G24(8.8,4.8) G25(9.6,4.8) H1(-9.6,4) H2(-8.8,4) H3(-8,4) H4(-7.2,4) H5(-6.4,4) H6(-5.6,4) H7(-4.8,4) H8(-4,4) H9(-3.2,4) H10(-2.4,4) H11(-1.6,4) H12(-0.8,4) H13(0,4) H14(0.8,4) H15(1.6,4) H16(2.4,4) H17(3.2,4) H18(4,4) H19(4.8,4) H20(5.6,4) H21(6.4,4) H22(7.2,4) H23(8,4) H24(8.8,4) H25(9.6,4) J1(-9.6,3.2) J2(-8.8,3.2) J3(-8,3.2) J4(-7.2,3.2) J5(-6.4,3.2) J6(-5.6,3.2) J7(-4.8,3.2) J8(-4,3.2) J9(-3.2,3.2) J10(-2.4,3.2) J11(-1.6,3.2) J12(-0.8,3.2) J13(0,3.2) J14(0.8,3.2) J15(1.6,3.2) J16(2.4,3.2) J17(3.2,3.2) J18(4,3.2) J19(4.8,3.2) J20(5.6,3.2) J21(6.4,3.2) J22(7.2,3.2) J23(8,3.2) J24(8.8,3.2) J25(9.6,3.2) K1(-9.6,2.4) K2(-8.8,2.4) K3(-8,2.4) K4(-7.2,2.4) K5(-6.4,2.4) K6(-5.6,2.4) K7(-4.8,2.4) K8(-4,2.4) K9(-3.2,2.4) K10(-2.4,2.4) K11(-1.6,2.4) K12(-0.8,2.4) K13(0,2.4) K14(0.8,2.4) K15(1.6,2.4) K16(2.4,2.4) K17(3.2,2.4) K18(4,2.4) K19(4.8,2.4) K20(5.6,2.4) K21(6.4,2.4) K22(7.2,2.4) K23(8,2.4) K24(8.8,2.4) K25(9.6,2.4) L1(-9.6,1.6) L2(-8.8,1.6) L3(-8,1.6) L4(-7.2,1.6) L5(-6.4,1.6) L6(-5.6,1.6) L7(-4.8,1.6) L8(-4,1.6) L9(-3.2,1.6) L10(-2.4,1.6) L11(-1.6,1.6) L12(-0.8,1.6) L13(0,1.6) L14(0.8,1.6) L15(1.6,1.6) L16(2.4,1.6) L17(3.2,1.6) L18(4,1.6) L19(4.8,1.6) L20(5.6,1.6) L21(6.4,1.6) L22(7.2,1.6) L23(8,1.6) L24(8.8,1.6) L25(9.6,1.6) M1(-9.6,0.8) M2(-8.8,0.8) M3(-8,0.8) M4(-7.2,0.8) M5(-6.4,0.8) M6(-5.6,0.8) M7(-4.8,0.8) M8(-4,0.8) M9(-3.2,0.8) M10(-2.4,0.8) M11(-1.6,0.8) M12(-0.8,0.8) M13(0,0.8) M14(0.8,0.8) M15(1.6,0.8) M16(2.4,0.8) M17(3.2,0.8) M18(4,0.8) M19(4.8,0.8) M20(5.6,0.8) M21(6.4,0.8) M22(7.2,0.8) M23(8,0.8) M24(8.8,0.8) M25(9.6,0.8) N1(-9.6,0) N2(-8.8,0) N3(-8,0) N4(-7.2,0) N5(-6.4,0) N6(-5.6,0) N7(-4.8,0) N8(-4,0) N9(-3.2,0) N10(-2.4,0) N11(-1.6,0) N12(-0.8,0) N13(0,0) N14(0.8,0) N15(1.6,0) N16(2.4,0) N17(3.2,0) N18(4,0) N19(4.8,0) N20(5.6,0) N21(6.4,0) N22(7.2,0) N23(8,0) N24(8.8,0) N25(9.6,0) P1(-9.6,-0.8) P2(-8.8,-0.8) P3(-8,-0.8) P4(-7.2,-0.8) P5(-6.4,-0.8) P6(-5.6,-0.8) P7(-4.8,-0.8) P8(-4,-0.8) P9(-3.2,-0.8) P10(-2.4,-0.8) P11(-1.6,-0.8) P12(-0.8,-0.8) P13(0,-0.8) P14(0.8,-0.8) P15(1.6,-0.8) P16(2.4,-0.8) P17(3.2,-0.8) P18(4,-0.8) P19(4.8,-0.8) P20(5.6,-0.8) P21(6.4,-0.8) P22(7.2,-0.8) P23(8,-0.8) P24(8.8,-0.8) P25(9.6,-0.8) R1(-9.6,-1.6) R2(-8.8,-1.6) R3(-8,-1.6) R4(-7.2,-1.6) R5(-6.4,-1.6) R6(-5.6,-1.6) R7(-4.8,-1.6) R8(-4,-1.6) R9(-3.2,-1.6) R10(-2.4,-1.6) R11(-1.6,-1.6) R12(-0.8,-1.6) R13(0,-1.6) R14(0.8,-1.6) R15(1.6,-1.6) R16(2.4,-1.6) R17(3.2,-1.6) R18(4,-1.6) R19(4.8,-1.6) R20(5.6,-1.6) R21(6.4,-1.6) R22(7.2,-1.6) R23(8,-1.6) R24(8.8,-1.6) R25(9.6,-1.6) T1(-9.6,-2.4) T2(-8.8,-2.4) T3(-8,-2.4) T4(-7.2,-2.4) T5(-6.4,-2.4) T6(-5.6,-2.4) T7(-4.8,-2.4) T8(-4,-2.4) T9(-3.2,-2.4) T10(-2.4,-2.4) T11(-1.6,-2.4) T12(-0.8,-2.4) T13(0,-2.4) T14(0.8,-2.4) T15(1.6,-2.4) T16(2.4,-2.4) T17(3.2,-2.4) T18(4,-2.4) T19(4.8,-2.4) T20(5.6,-2.4) T21(6.4,-2.4) T22(7.2,-2.4) T23(8,-2.4) T24(8.8,-2.4) T25(9.6,-2.4) U1(-9.6,-3.2) U2(-8.8,-3.2) U3(-8,-3.2) U4(-7.2,-3.2) U5(-6.4,-3.2) U6(-5.6,-3.2) U7(-4.8,-3.2) U8(-4,-3.2) U9(-3.2,-3.2) U10(-2.4,-3.2) U11(-1.6,-3.2) U12(-0.8,-3.2) U13(0,-3.2) U14(0.8,-3.2) U15(1.6,-3.2) U16(2.4,-3.2) U17(3.2,-3.2) U18(4,-3.2) U19(4.8,-3.2) U20(5.6,-3.2) U21(6.4,-3.2) U22(7.2,-3.2) U23(8,-3.2) U24(8.8,-3.2) U25(9.6,-3.2) V1(-9.6,-4) V2(-8.8,-4) V3(-8,-4) V4(-7.2,-4) V5(-6.4,-4) V6(-5.6,-4) V7(-4.8,-4) V8(-4,-4) V9(-3.2,-4) V10(-2.4,-4) V11(-1.6,-4) V12(-0.8,-4) V13(0,-4) V14(0.8,-4) V15(1.6,-4) V16(2.4,-4) V17(3.2,-4) V18(4,-4) V19(4.8,-4) V20(5.6,-4) V21(6.4,-4) V22(7.2,-4) V23(8,-4) V24(8.8,-4) V25(9.6,-4) W1(-9.6,-4.8) W2(-8.8,-4.8) W3(-8,-4.8) W4(-7.2,-4.8) W5(-6.4,-4.8) W6(-5.6,-4.8) W7(-4.8,-4.8) W8(-4,-4.8) W9(-3.2,-4.8) W10(-2.4,-4.8) W11(-1.6,-4.8) W12(-0.8,-4.8) W13(0,-4.8) W14(0.8,-4.8) W15(1.6,-4.8) W16(2.4,-4.8) W17(3.2,-4.8) W18(4,-4.8) W19(4.8,-4.8) W20(5.6,-4.8) W21(6.4,-4.8) W22(7.2,-4.8) W23(8,-4.8) W24(8.8,-4.8) W25(9.6,-4.8) Y1(-9.6,-5.6) Y2(-8.8,-5.6) Y3(-8,-5.6) Y4(-7.2,-5.6) Y5(-6.4,-5.6) Y6(-5.6,-5.6) Y7(-4.8,-5.6) Y8(-4,-5.6) Y9(-3.2,-5.6) Y10(-2.4,-5.6) Y11(-1.6,-5.6) Y12(-0.8,-5.6) Y13(0,-5.6) Y14(0.8,-5.6) Y15(1.6,-5.6) Y16(2.4,-5.6) Y17(3.2,-5.6) Y18(4,-5.6) Y19(4.8,-5.6) Y20(5.6,-5.6) Y21(6.4,-5.6) Y22(7.2,-5.6) Y23(8,-5.6) Y24(8.8,-5.6) Y25(9.6,-5.6)
Top Overlay:
  circle w0.2: c-10.976,9.6 r0.1
  region: -9.856,10.576 -10.576,9.856 -10.576,10.576
  lines w0.152: -10.805,9.856 -10.805,10.805 -9.856,10.805 ; -10.576,-10.576 -10.576,10.576 10.576,10.576 10.576,-10.576 -10.576,-10.576
Mechanical 2:
  circle w0.2: c-9.7,9.6 r0.1
  region: -9.525,10.541 -10.541,10.541 -10.541,9.525
Mechanical 6:
  lines w0.051: -10.5,-10.5 -10.5,10.5 10.5,10.5 10.5,-10.5 -10.5,-10.5
Mechanical 8:
  region: -10.44,10.5 -10.44,10.475 -10.475,10.44 -10.525,10.44 -10.56,10.475 -10.56,10.5 -10.56,10.525 -10.525,10.56 -10.475,10.56 -10.44,10.525 -10.44,10.5
Mechanical 9:
  drawing of 624 lines, arcs and shapes, not listed
3D body "FCPBGA-624_L21.0-W21.0-R25-C25-P0.80-TL-PE_A1.step": height 1.61, standoff -0.4, extent -10.5,-10.5 10.5,10.5

## FILTER-SMD_6P-L4.5-W3.4_GA021G00 [mm]
pads (6):
  rect 1.4x0.5 smd paste+0 mask+0.05: 1(-1.8,-1.438) 2(-1.8,-0.637) 4(1.8,1.438) 5(1.8,0.637)
  rect 1.4x0.65 smd paste+0 mask+0.05: 3(-1.8,1.438) 6(1.8,-1.438)
Top Overlay:
  circle w0.254: c-0.508,-1.143 r0.127
  lines w0.254: -2.286,-0.156 -2.286,0.956 ; -0.869,-1.651 0.869,-1.651 ; -0.869,1.651 0.869,1.651 ; 2.286,-0.956 2.286,0.156
Mechanical 6:
  lines w0.051: -2.3,-1.7 2.3,-1.7 2.3,1.7 -2.3,1.7 -2.3,-1.7
Mechanical 8:
  region: -2.24,-1.7 -2.24,-1.725 -2.275,-1.76 -2.325,-1.76 -2.36,-1.725 -2.36,-1.7 -2.36,-1.675 -2.325,-1.64 -2.275,-1.64 -2.24,-1.675 -2.24,-1.7
Mechanical 9:
  region: 1.3,0.862 2.3,0.862 2.3,0.412 1.3,0.412
  region: 1.3,1.663 2.3,1.663 2.3,1.213 1.3,1.213
  region: -2.3,-1.213 -1.3,-1.213 -1.3,-1.663 -2.3,-1.663
  region: -2.3,-0.412 -1.3,-0.412 -1.3,-0.862 -2.3,-0.862
  region: -2.3,1.7 -1.3,1.7 -1.3,1.1 -2.3,1.1
  region: 1.3,-1.1 2.3,-1.1 2.3,-1.7 1.3,-1.7
3D body "XFMR-SMD_6P-L4.6-W3.4_MA021G00.step": height 3.16, standoff -0.05, extent -2.3,-1.7 2.31,1.7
